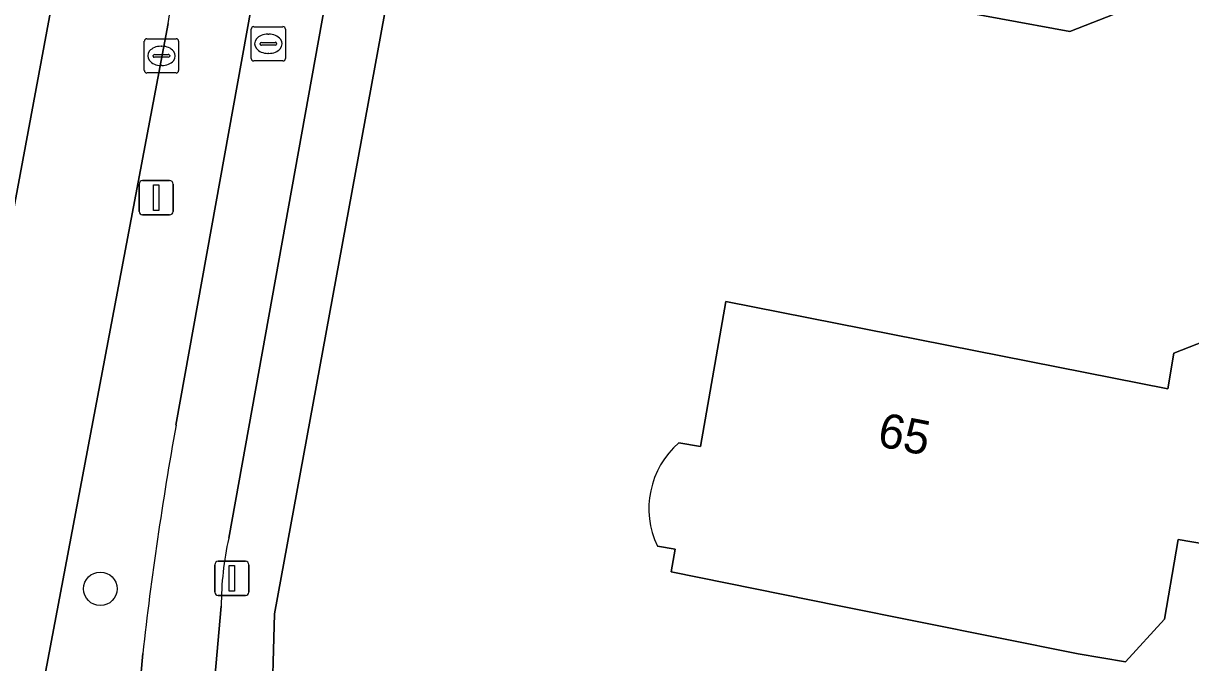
# Model space of a CAD drawing. Extents: x 161692 to 162379, y 380760 to 381678.
# Drawn here: x 161752.37 to 161786.45, y 381139.1 to 381157.75 of the extents above; entities that cross this region are included whole.
import ezdxf

# ---------------------------------------------------------------- set-up
doc = ezdxf.new("R2010")
doc.units = 0
for name, color, linetype in [('IMGEO_Boom', 7, 'Continuous'), ('IMGEO_Erf', 7, 'Continuous'), ('IMGEO_Fietspad_gesloten', 7, 'Continuous'), ('IMGEO_Kolk', 7, 'Continuous'), ('IMGEO_Lichtmast', 7, 'Continuous'), ('IMGEO_OVBaan_gesloten', 7, 'Continuous'), ('IMGEO_Pand', 7, 'Continuous'), ('IMGEO_Pand_nummerreeks', 7, 'Continuous'), ('IMGEO_Rijbaan_regionaal_gesloten', 7, 'Continuous'), ('IMGEO_Rioolput', 7, 'Continuous'), ('IMGEO_Verkeerseiland_groen', 7, 'Continuous'), ('IMGEO_Voetpad_open', 7, 'Continuous')]:
    doc.layers.add(name, color=color, linetype=linetype)

msp = doc.modelspace()

# ---------------------------------------------------------------- linework, layer by layer
at = {"layer": 'IMGEO_Boom'}
msp.add_circle((161754.619, 381141.251), 0.489, dxfattribs=at)
at = {"layer": 'IMGEO_Erf'}
for points in [[(161854.96, 381119.298), (161852.88, 381124.681), (161833.302, 381175.355), (161830.972, 381176.303), (161782.92, 381157.51), (161766.802, 381160.481), (161766.378, 381160.559)], [(161763.075, 381158.749), (161762.918, 381158.007), (161759.702, 381140.521), (161759.617, 381137.351), (161757.191, 381111.169)], [(161771.508, 381145.514), (161772.14, 381145.404), (161772.875, 381149.629), (161785.778, 381147.09), (161785.958, 381148.122), (161788.817, 381149.241), (161790.638, 381144.585), (161791.046, 381143.542), (161788.015, 381142.356), (161786.084, 381142.692), (161786.025, 381142.351), (161785.681, 381140.36), (161784.544, 381139.116), (161783.163, 381139.356), (161776.183, 381140.758), (161771.28, 381141.743)], [(161771.28, 381141.743), (161771.395, 381142.406), (161770.881, 381142.495)]]:
    msp.add_lwpolyline(points, dxfattribs=at)
msp.add_arc((161773.171, 381143.594), 2.54, 130.8907, 205.644, dxfattribs=at)
at = {"layer": 'IMGEO_Fietspad_gesloten'}
for points in [[(161758.366, 381142.727), (161761.764, 381161.581), (161759.699, 381161.956), (161759.664, 381161.765), (161756.827, 381146.025)], [(161755.855, 381139.363), (161755.73, 381137.951), (161755.369, 381133.869), (161752.9, 381105.932), (161752.925, 381105.216), (161755.105, 381105.291), (161755.078, 381106.072), (161758.146, 381140.74)]]:
    msp.add_lwpolyline(points, dxfattribs=at)
for centre, radius, start, end in [((161859.018, 381127.713), 103.818, 169.84088, 173.55711), ((161767.726, 381140.685), 9.58, 167.6929, 179.671)]:
    msp.add_arc(centre, radius, start, end, dxfattribs=at)
at = {"layer": 'IMGEO_Kolk'}
for p, q in [((161755.903, 381156.375), (161755.903, 381157.227)), ((161755.978, 381157.301), (161756.83, 381157.301)), ((161756.904, 381157.227), (161756.904, 381156.375)), ((161756.391, 381157.081), (161756.416, 381157.081)), ((161756.162, 381156.795), (161756.162, 381156.807)), ((161756.6, 381156.758), (161756.202, 381156.758)), ((161756.205, 381156.844), (161756.603, 381156.844)), ((161756.414, 381156.521), (161756.389, 381156.521)), ((161756.646, 381156.807), (161756.646, 381156.795)), ((161756.83, 381156.301), (161755.978, 381156.301))]:
    msp.add_line(p, q, dxfattribs=at)
for points in [[(161755.903, 381156.375), (161755.903, 381157.227)], [(161755.978, 381157.301), (161756.83, 381157.301)], [(161756.904, 381157.227), (161756.904, 381156.375)], [(161756.83, 381156.301), (161755.978, 381156.301)]]:
    msp.add_lwpolyline(points, dxfattribs=at)
for centre, radius, start, end in [((161755.98, 381157.225), 0.0765, 91.552, 178.448), ((161755.98, 381157.225), 0.0765, 91.552, 178.448), ((161756.828, 381157.225), 0.0765, 1.552, 88.448), ((161756.828, 381157.225), 0.0765, 1.552, 88.448), ((161756.202, 381156.804), 0.0403, 85.8775, 175.7526), ((161756.199, 381156.794), 0.0366, 178.938, 274.7102), ((161756.603, 381156.801), 0.043, 264.8664, 352.4533), ((161756.607, 381156.806), 0.0386, 1.7309, 96.639), ((161755.98, 381156.377), 0.0765, 181.552, 268.448), ((161755.98, 381156.377), 0.0765, 181.552, 268.448), ((161756.828, 381156.377), 0.0765, 271.552, 358.448), ((161756.828, 381156.377), 0.0765, 271.552, 358.448)]:
    msp.add_arc(centre, radius, start, end, dxfattribs=at)
for centre, major_axis, ratio, start_param, end_param in [((161756.39, 381156.801), (-0.387, 0.002), 0.722429, 4.712389, 7.853982), ((161756.415, 381156.801), (-0.39, 0.002), 0.717154, 1.570796, 4.712389)]:
    msp.add_ellipse(centre, major_axis=major_axis, ratio=ratio, start_param=start_param, end_param=end_param, dxfattribs=at)
at = {"layer": 'IMGEO_Lichtmast'}
for p, q in [((161755.852, 381153.161), (161756.642, 381153.161)), ((161756.642, 381153.161), (161755.852, 381153.161)), ((161755.752, 381152.261), (161755.752, 381153.061)), ((161755.752, 381153.061), (161755.752, 381152.261)), ((161756.742, 381153.061), (161756.742, 381152.261)), ((161756.742, 381152.261), (161756.742, 381153.061)), ((161756.642, 381152.161), (161755.852, 381152.161)), ((161755.852, 381152.161), (161756.642, 381152.161)), ((161757.962, 381141.154), (161757.962, 381141.954)), ((161757.962, 381141.954), (161757.962, 381141.154)), ((161758.062, 381142.054), (161758.852, 381142.054)), ((161758.852, 381142.054), (161758.062, 381142.054)), ((161758.952, 381141.954), (161758.952, 381141.154)), ((161758.952, 381141.154), (161758.952, 381141.954)), ((161758.852, 381141.054), (161758.062, 381141.054)), ((161758.062, 381141.054), (161758.852, 381141.054))]:
    msp.add_line(p, q, dxfattribs=at)
for points in [[(161756.172, 381153.036), (161756.322, 381153.036), (161756.322, 381152.286), (161756.172, 381152.286), (161756.172, 381153.036)], [(161758.382, 381141.929), (161758.532, 381141.929), (161758.532, 381141.179), (161758.382, 381141.179), (161758.382, 381141.929)]]:
    msp.add_lwpolyline(points, dxfattribs=at)
for centre, start, end in [((161755.852, 381153.061), 90, 180), ((161755.852, 381153.061), 90, 180), ((161756.642, 381153.061), 0, 90), ((161756.642, 381153.061), 360, 90), ((161755.852, 381152.261), 180, 270), ((161755.852, 381152.261), 180, 270), ((161756.642, 381152.261), 270, 0), ((161756.642, 381152.261), 270, 0), ((161758.062, 381141.954), 90, 180), ((161758.062, 381141.954), 90, 180), ((161758.852, 381141.954), 0, 90), ((161758.852, 381141.954), 360, 90), ((161758.062, 381141.154), 180, 270), ((161758.062, 381141.154), 180, 270), ((161758.852, 381141.154), 270, 0), ((161758.852, 381141.154), 270, 0)]:
    msp.add_arc(centre, 0.1, start, end, dxfattribs=at)
at = {"layer": 'IMGEO_OVBaan_gesloten'}
msp.add_lwpolyline([(161744.563, 381111.938), (161780.667, 381305.843), (161780.198, 381305.933), (161783.4, 381322.888), (161779.986, 381323.471), (161776.881, 381306.547), (161776.704, 381306.578), (161776.704, 381306.578), (161771.577, 381277.677), (161758.366, 381204.804), (161740.263, 381107.16), (161733.581, 381071.116)], dxfattribs=at)
at = {"layer": 'IMGEO_Pand'}
msp.add_lwpolyline([(161770.881, 381142.495), (161771.395, 381142.406), (161771.28, 381141.743), (161776.183, 381140.758), (161783.163, 381139.356), (161784.544, 381139.116), (161785.681, 381140.36), (161786.025, 381142.351), (161786.084, 381142.692), (161788.015, 381142.356), (161791.046, 381143.542), (161790.638, 381144.585), (161788.817, 381149.241), (161785.958, 381148.122), (161785.778, 381147.09), (161772.875, 381149.629), (161772.14, 381145.404), (161771.508, 381145.514)], dxfattribs=at)
msp.add_arc((161773.171, 381143.594), 2.54, 130.8907, 205.644, dxfattribs=at)
at = {"layer": 'IMGEO_Rijbaan_regionaal_gesloten'}
for points in [[(161779.709, 381323.516), (161779.709, 381323.516), (161779.986, 381323.471), (161783.4, 381322.888), (161783.872, 381322.811), (161780.667, 381305.843), (161744.563, 381111.938)], [(161750.039, 381122.715), (161750.703, 381126.559), (161752.161, 381134.28), (161752.921, 381138.304), (161756.594, 381157.749)]]:
    msp.add_lwpolyline(points, dxfattribs=at)
msp.add_arc((161763.934, 381156.938), 7.385, 142.6847, 173.6963, dxfattribs=at)
at = {"layer": 'IMGEO_Rioolput'}
for p, q in [((161759.023, 381156.726), (161759.023, 381157.578)), ((161759.098, 381157.652), (161759.95, 381157.652)), ((161760.024, 381157.578), (161760.024, 381156.726)), ((161759.325, 381157.195), (161759.723, 381157.195)), ((161759.511, 381157.432), (161759.536, 381157.432)), ((161759.282, 381157.146), (161759.282, 381157.158)), ((161759.72, 381157.109), (161759.322, 381157.109)), ((161759.534, 381156.872), (161759.509, 381156.872)), ((161759.766, 381157.158), (161759.766, 381157.146)), ((161759.95, 381156.652), (161759.098, 381156.652))]:
    msp.add_line(p, q, dxfattribs=at)
for points in [[(161759.023, 381156.726), (161759.023, 381157.578)], [(161759.098, 381157.652), (161759.95, 381157.652)], [(161760.024, 381157.578), (161760.024, 381156.726)], [(161759.95, 381156.652), (161759.098, 381156.652)]]:
    msp.add_lwpolyline(points, dxfattribs=at)
for centre, radius, start, end in [((161759.1, 381157.576), 0.0765, 91.552, 178.448), ((161759.1, 381157.576), 0.0765, 91.552, 178.448), ((161759.948, 381157.576), 0.0765, 1.552, 88.448), ((161759.948, 381157.576), 0.0765, 1.552, 88.448), ((161759.322, 381157.155), 0.0403, 85.8775, 175.7526), ((161759.727, 381157.157), 0.0386, 1.7309, 96.639), ((161759.319, 381157.145), 0.0366, 178.938, 274.7102), ((161759.723, 381157.152), 0.043, 264.8664, 352.4533), ((161759.1, 381156.728), 0.0765, 181.552, 268.448), ((161759.1, 381156.728), 0.0765, 181.552, 268.448), ((161759.948, 381156.728), 0.0765, 271.552, 358.448), ((161759.948, 381156.728), 0.0765, 271.552, 358.448)]:
    msp.add_arc(centre, radius, start, end, dxfattribs=at)
for centre, major_axis, ratio, start_param, end_param in [((161759.51, 381157.152), (-0.387, 0.002), 0.722429, 4.712389, 7.853982), ((161759.535, 381157.152), (-0.39, 0.002), 0.717154, 1.570796, 4.712389)]:
    msp.add_ellipse(centre, major_axis=major_axis, ratio=ratio, start_param=start_param, end_param=end_param, dxfattribs=at)
at = {"layer": 'IMGEO_Verkeerseiland_groen'}
for points in [[(161756.827, 381146.025), (161759.664, 381161.765)], [(161756.594, 381157.749), (161752.921, 381138.304), (161755.73, 381137.951), (161755.855, 381139.363)]]:
    msp.add_lwpolyline(points, dxfattribs=at)
for centre, radius, start, end in [((161763.934, 381156.938), 7.385, 142.6847, 173.6963), ((161859.018, 381127.713), 103.818, 169.84088, 173.55711)]:
    msp.add_arc(centre, radius, start, end, dxfattribs=at)
at = {"layer": 'IMGEO_Voetpad_open'}
for points in [[(161766.378, 381160.559), (161766.802, 381160.481), (161782.92, 381157.51), (161830.972, 381176.303), (161833.302, 381175.355), (161836.452, 381175.254), (161837.683, 381175.784)], [(161757.191, 381111.169), (161759.617, 381137.351), (161759.702, 381140.521), (161762.918, 381158.007), (161763.075, 381158.749), (161764.167, 381163.904)], [(161761.764, 381161.581), (161758.366, 381142.727)], [(161758.146, 381140.74), (161755.078, 381106.072), (161755.105, 381105.291)]]:
    msp.add_lwpolyline(points, dxfattribs=at)
msp.add_arc((161767.726, 381140.685), 9.58, 167.6929, 179.671, dxfattribs=at)

# ---------------------------------------------------------------- texts
at = {"layer": 'IMGEO_Pand_nummerreeks'}
msp.add_text('65', height=1, rotation=348.8678, dxfattribs=at).set_placement((161777.268, 381145.422))

doc.saveas('drawing.dxf')
